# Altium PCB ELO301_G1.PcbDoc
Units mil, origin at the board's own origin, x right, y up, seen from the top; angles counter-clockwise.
Board outline 2755.91 x 1968.5 mil, 4 copper layers (Top Layer, GND, Senal-Potencia, Bottom Layer), stack 62.449 mil thick; 68 components, 51 nets, 254 pads, 188 vias.
Unrouted connection lines stored in the file: 32.
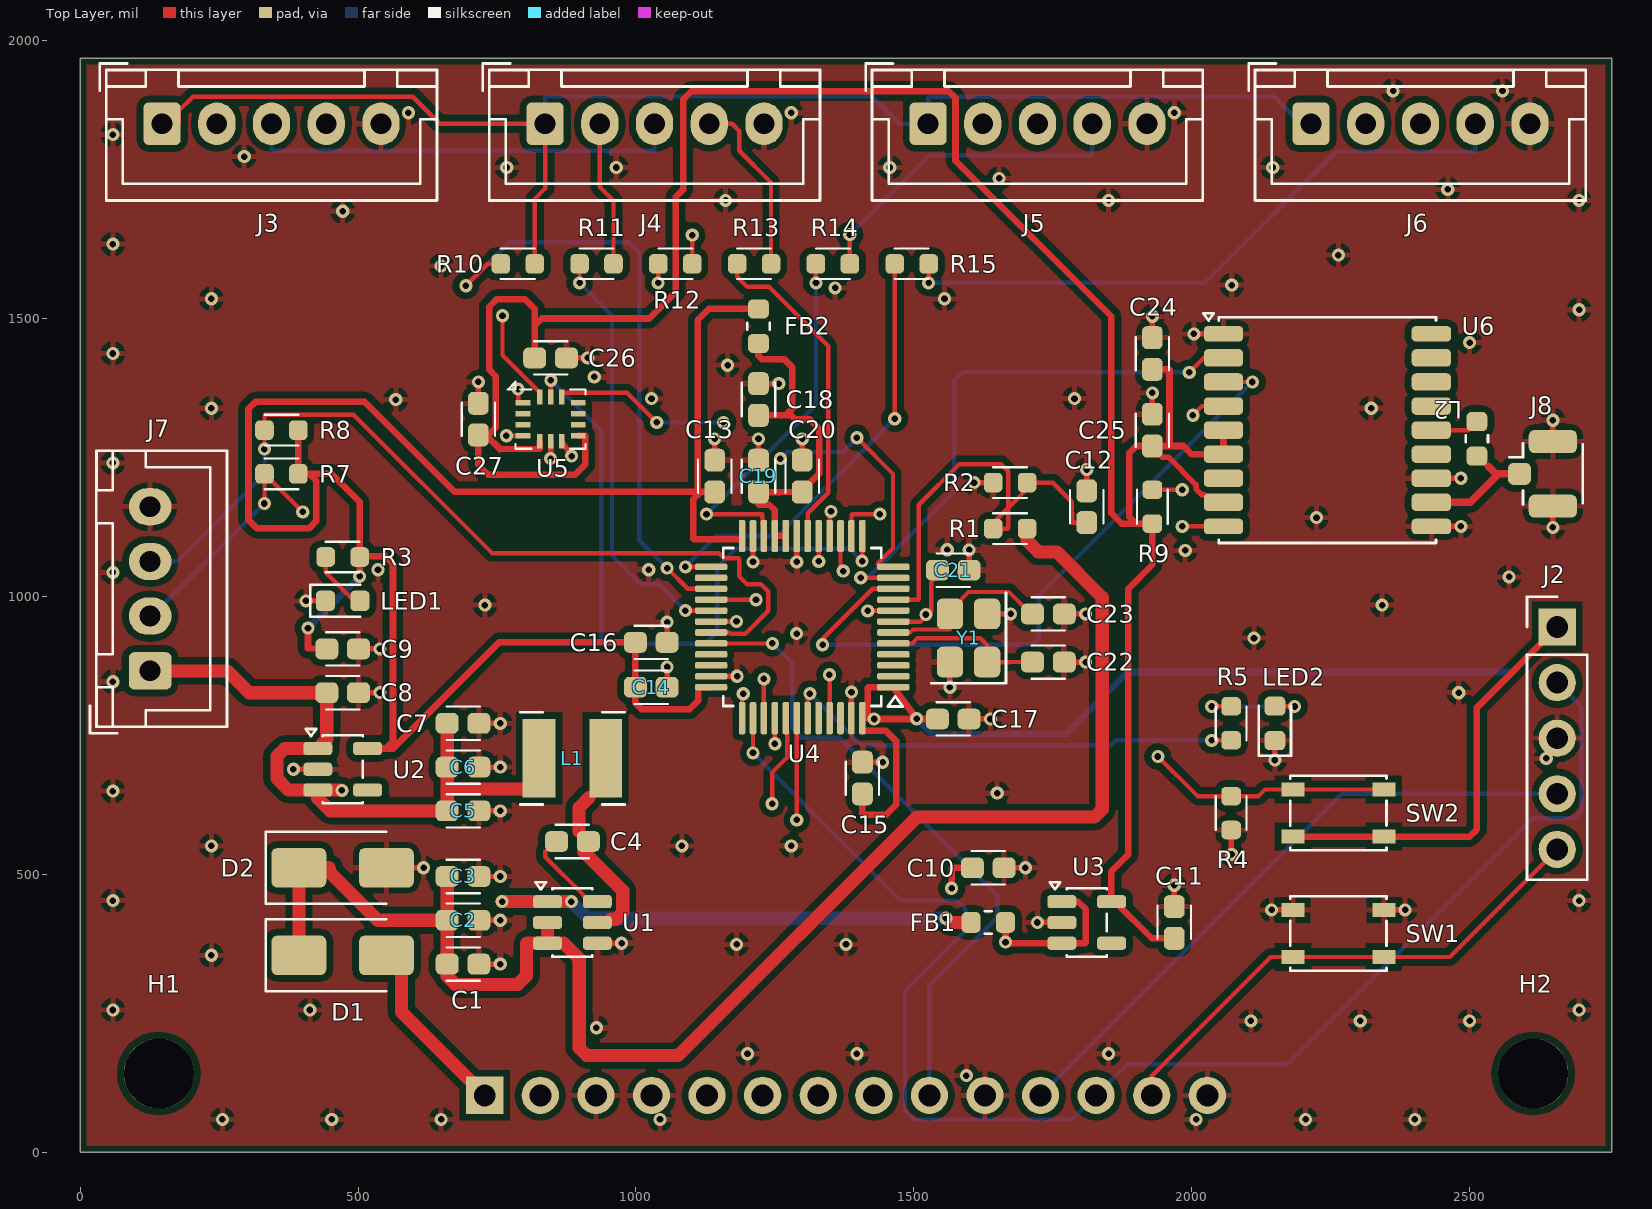
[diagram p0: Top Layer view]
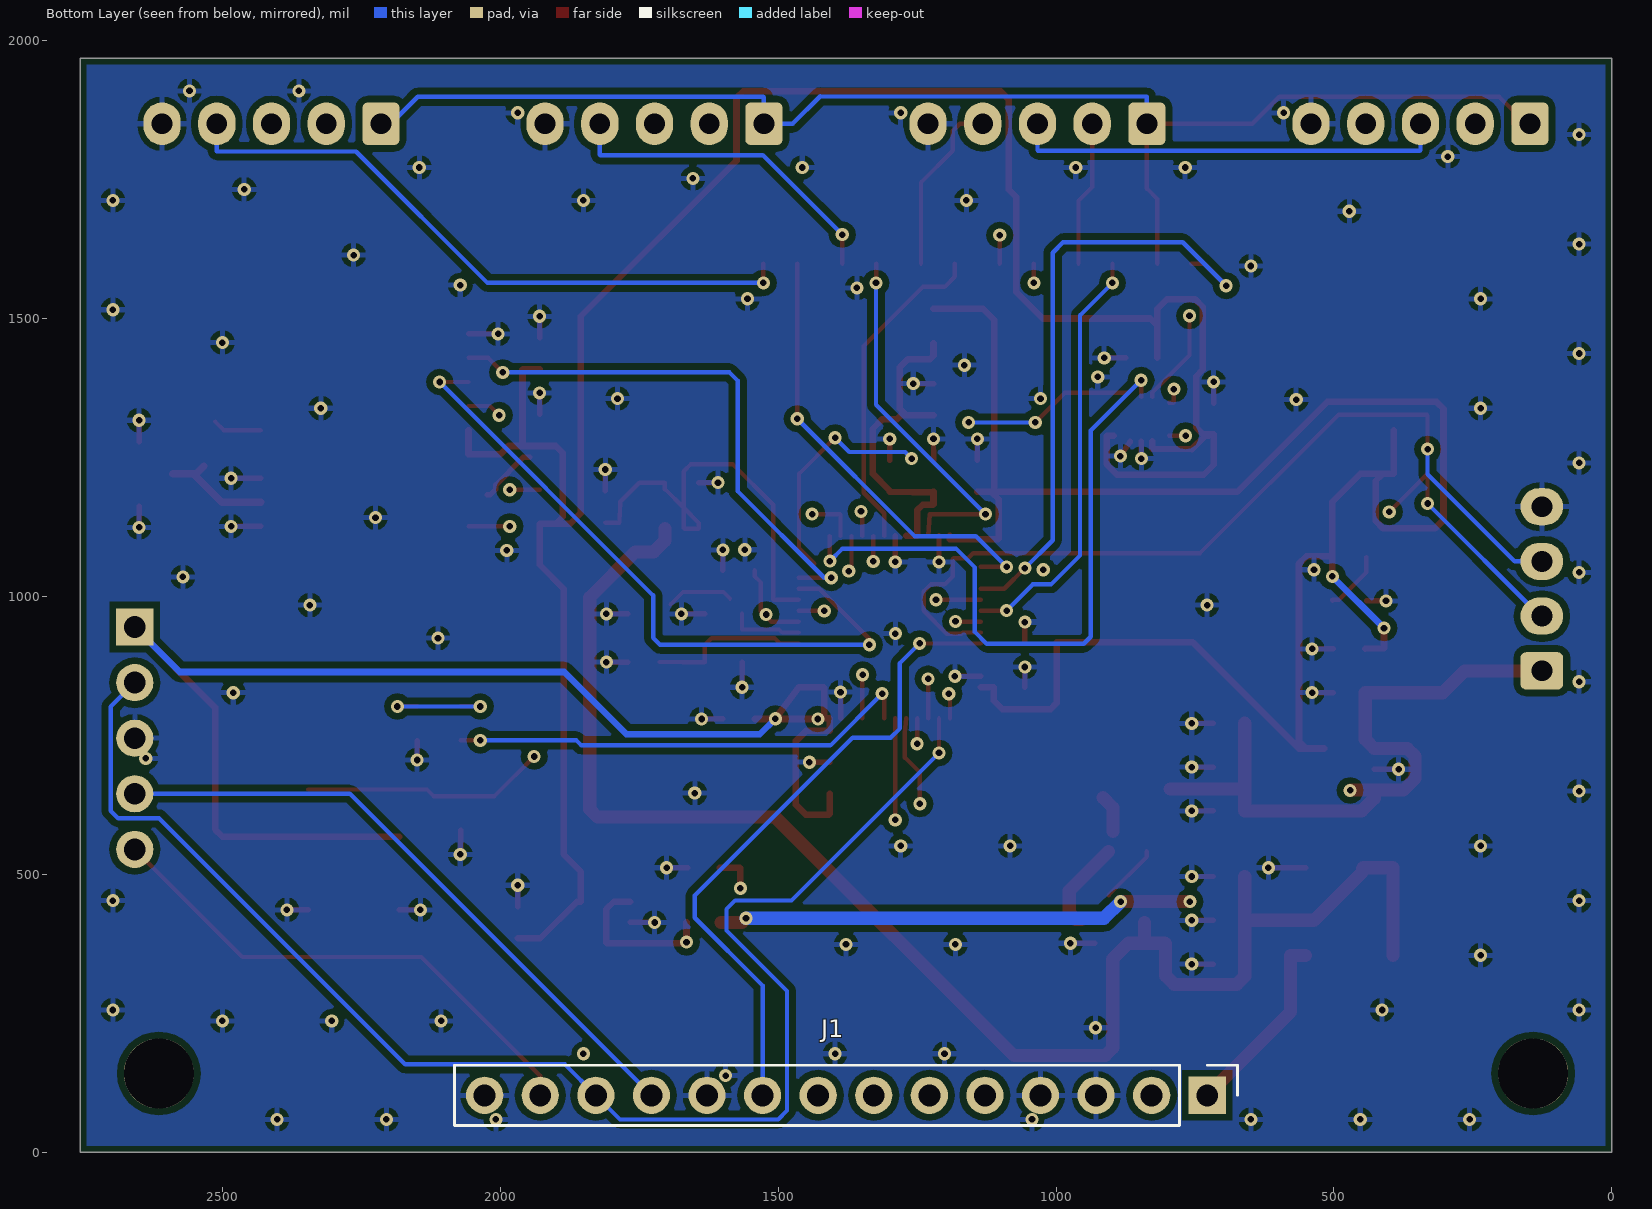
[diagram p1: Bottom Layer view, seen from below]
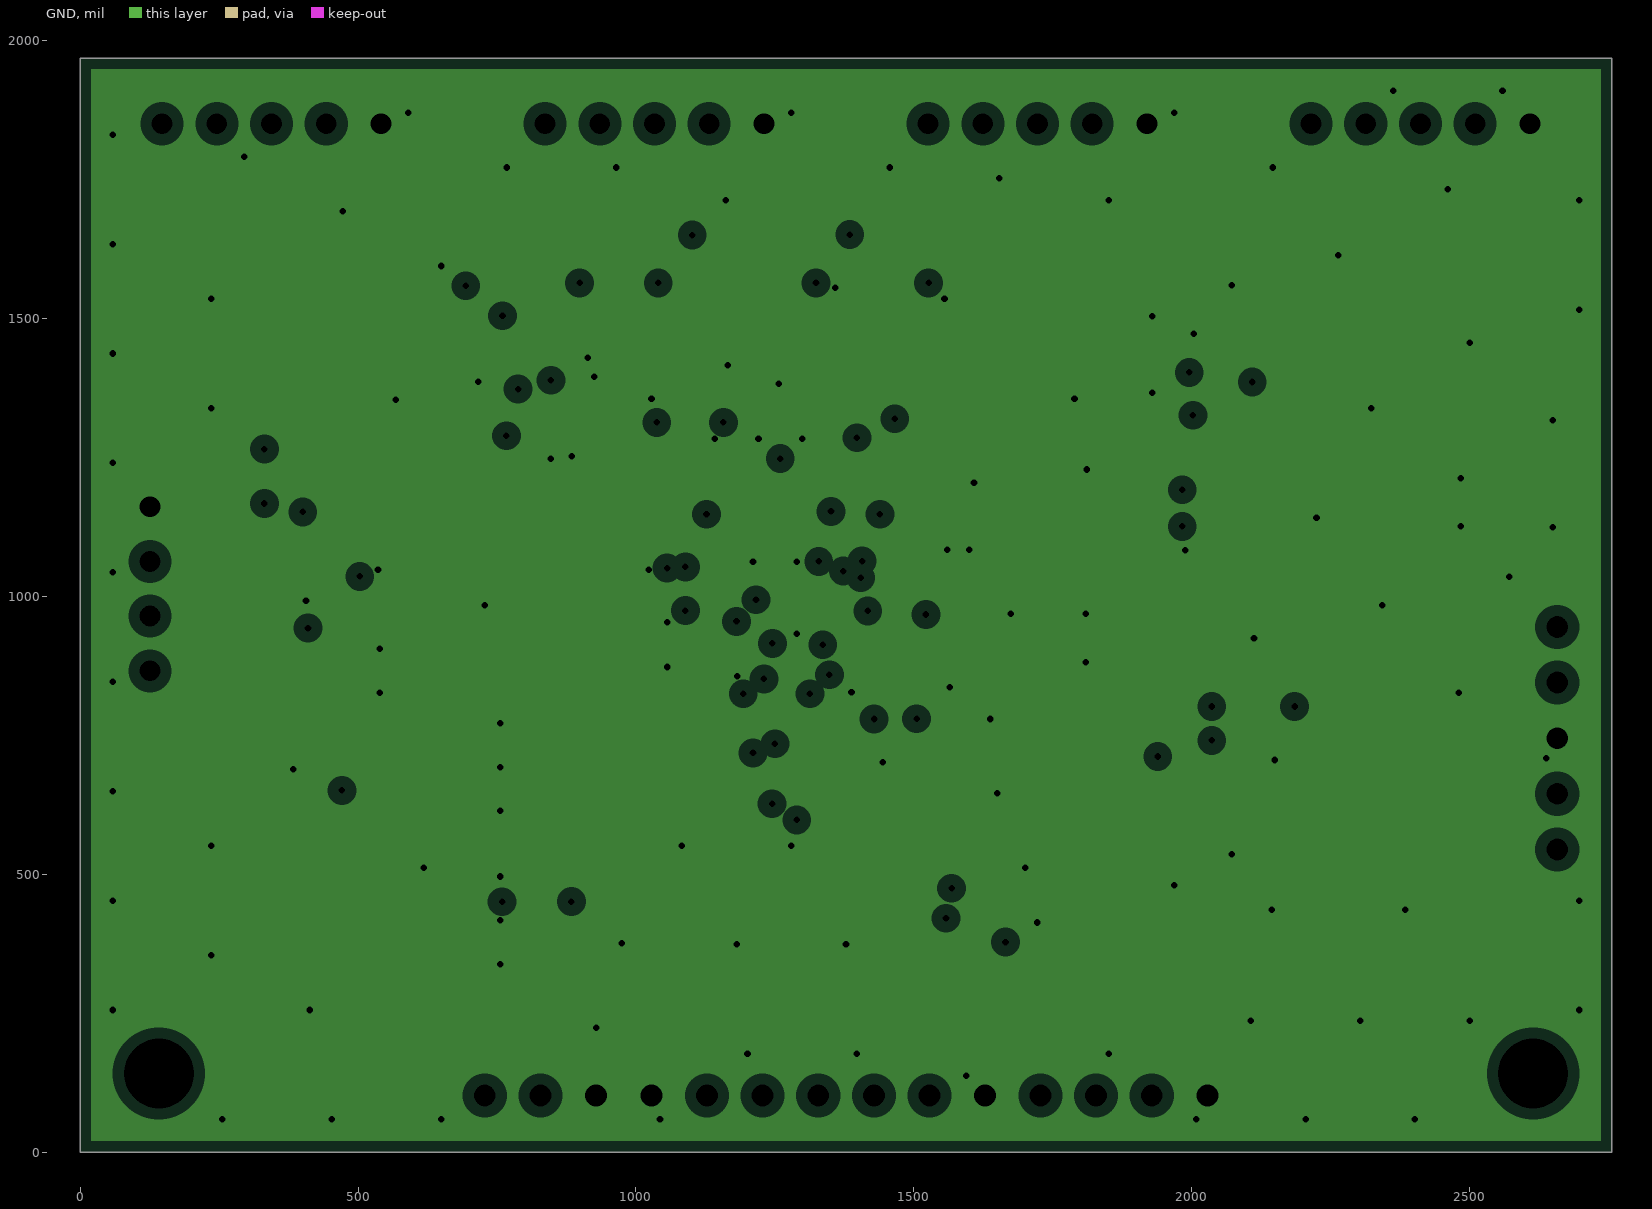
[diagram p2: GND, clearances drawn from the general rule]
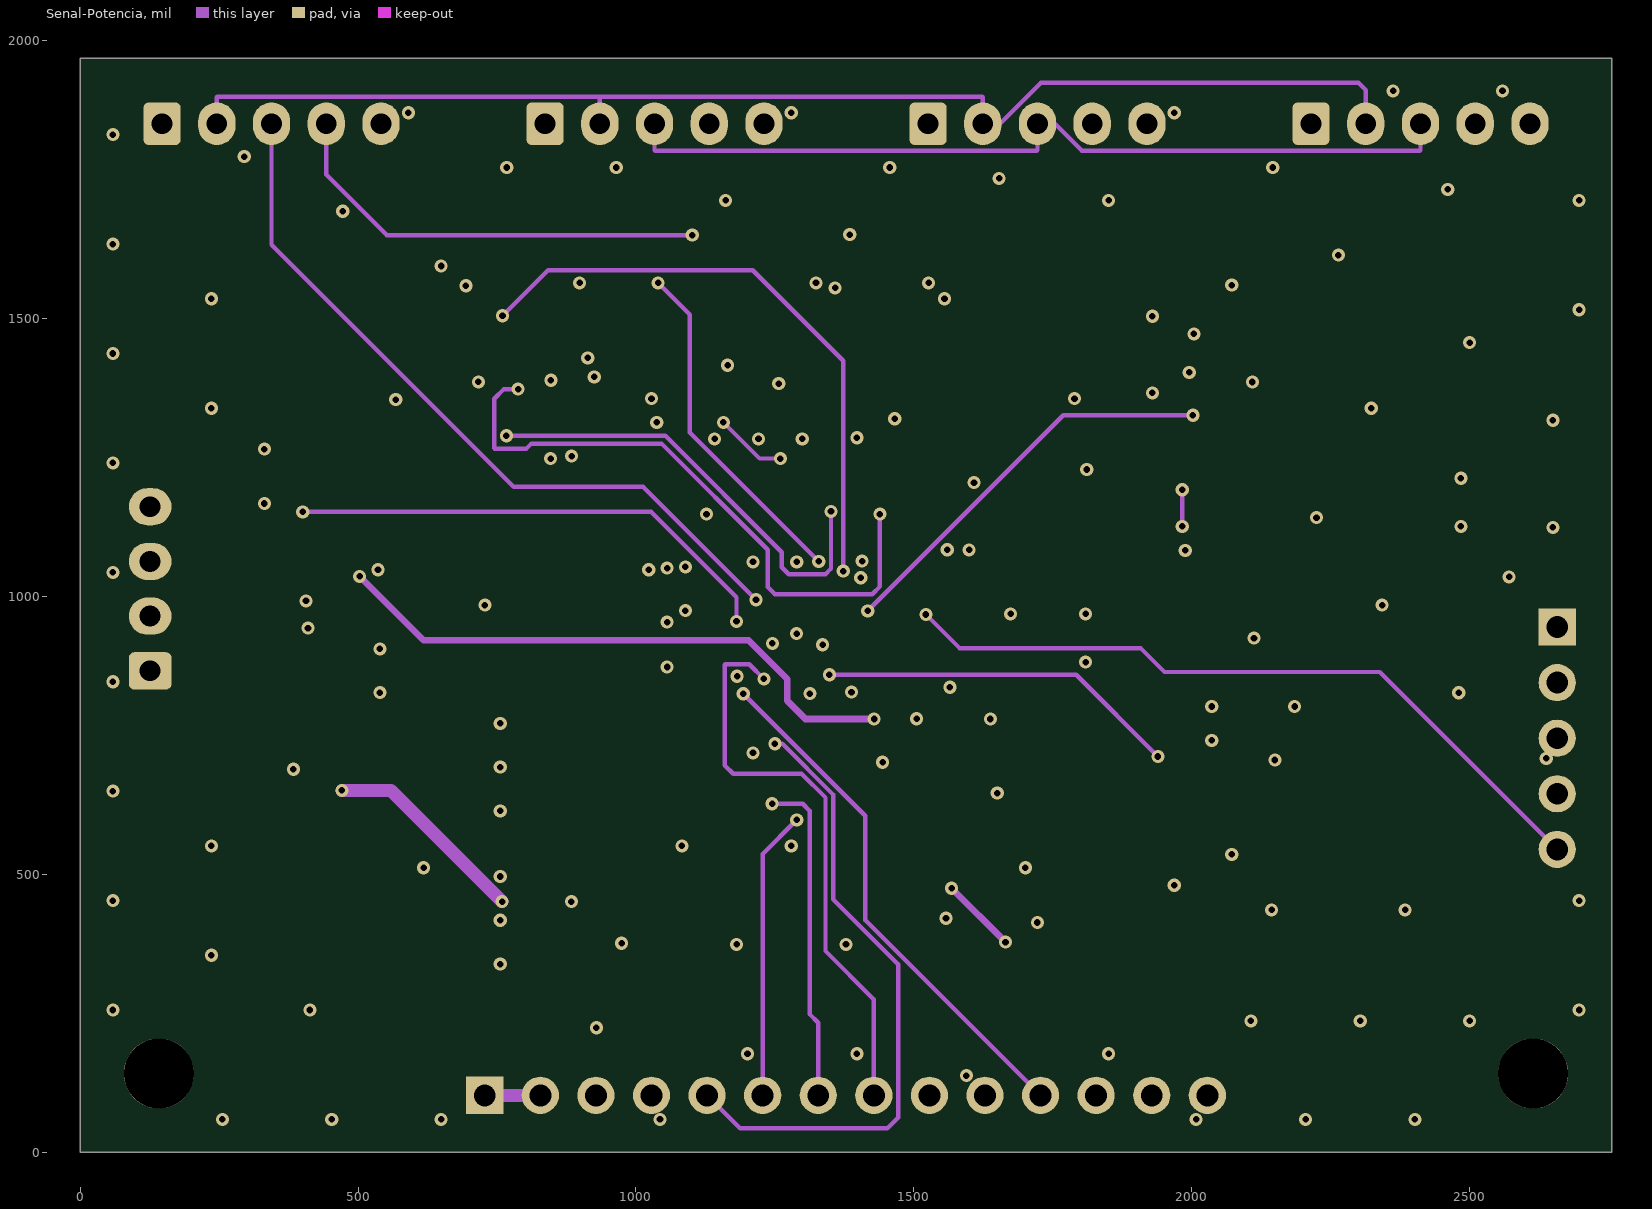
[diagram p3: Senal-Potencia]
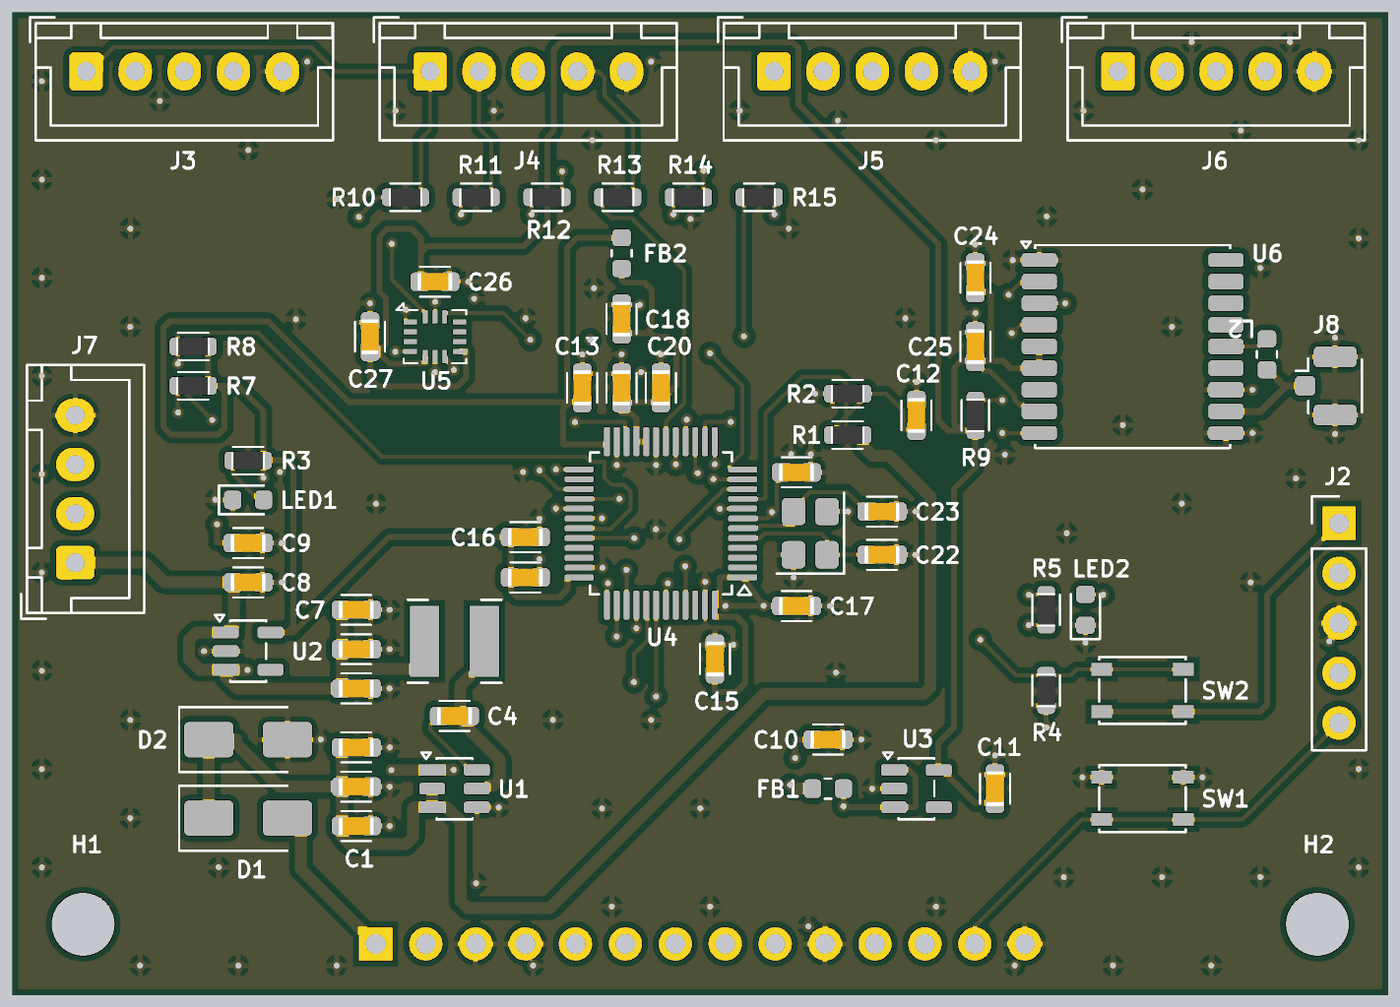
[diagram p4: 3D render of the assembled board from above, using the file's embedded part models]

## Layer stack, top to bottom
Top Solder: solder mask 0.4, Solder Resist, Dk 3.5
Top Layer: signal copper 1.378
Dielectric 1: prepreg 8.2835, PP 7628, Dk 4.4
GND: plane copper 0.5984, net GND
Dielectric2: core 41.9291, FR-4, Dk 4.6
Senal-Potencia: signal copper 0.5984
Dielectric3: prepreg 8.2835, PP 7628, Dk 4.4
Bottom Layer: signal copper 1.378
Bottom Solder: solder mask 0.4, Solder Resist, Dk 3.5

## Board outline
0,0 0,1968.5 2755.91,1968.5 2755.91,0

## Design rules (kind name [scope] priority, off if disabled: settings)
Clearance Clearance_Poligono [InPolygon] p1: gap=11.81 ignorepadtopadclearanceinfootprint=FALSE
Clearance [All] p2: gap=5.91 ignorepadtopadclearanceinfootprint=FALSE
HoleSize [All] p1: absolutevalues=TRUE maxlimit=137.8 minlimit=9.84 maxpercent=80.000 minpercent=20.000
MinimumSolderMaskSliver [All] p1: minsoldermaskwidth=2.76
PlaneClearance [All] p1: clearance=20
PlaneConnect [All] p1: planeconnectstyle=Relief reliefexpansion=20 reliefentries=4 reliefconductorwidth=10 reliefairgap=10
PolygonConnect [All] p1: connectstyle=Relief reliefconductorwidth=10 reliefentries=4 polygonreliefangle="90 Angle" airgapwidth=10
RoutingVias [All] p1: holewidth=11.81 width=23.62 viastyle="Through Hole" minholewidth=9.84 minwidth=19.68 maxholewidth=15.75 maxwidth=31.5
SilkToSolderMaskClearance [IsPad] p1: minsilkscreentomaskgap=3.94 clearancetoexposedcopper=TRUE
SolderMaskExpansion [All] p1: expansion=1.97 istentingtop=FALSE
SupplyNets "Schematic Supply Nets_3" [InNet('V_5V')] p1: voltage=0.000
SupplyNets "Schematic Supply Nets_2" [InNet('GND')] p2: voltage=0.000
SupplyNets "Schematic Supply Nets_1" [InNet('V3V3_MCU')] p3: voltage=0.000
SupplyNets "Schematic Supply Nets" [InNet('V3V3_SENS')] p4: voltage=0.000
Width Ancho_RF [InNet('RF_IN')] p1: maxlimit=13.78 minlimit=13.78 preferedwidth=13.78 minimp=50.000000 maximp=50.000000 favimp=50.000000
Width Ancho_Potencia [InNetClass('Potencia')] p2: maxlimit=78.74 minlimit=11.81 preferedwidth=23.62 minimp=50.000000 maximp=50.000000 favimp=50.000000
Width Ancho_Alimentacion [InNetClass('Alimentacion')] p3: maxlimit=78.74 minlimit=9.84 preferedwidth=11.81 minimp=50.000000 maximp=50.000000 favimp=50.000000
Width [All] p4: maxlimit=78.74 minlimit=5.91 preferedwidth=7.87 minimp=50.000000 maximp=50.000000 favimp=50.000000
25 further rules are at their usual default settings.

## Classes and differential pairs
net class Alimentacion: V3V3_MCU V3V3_SENS V5_SENS VDDA
net class Potencia: SW V_5V VIN_12V VIN_PROT
component class 04_Conectores: H1 H2 J1 J2 J3 J4 J5 J6 R10 R11 R12 R13 R14 R15
component class 03_Sensores: C24 C25 C26 C27 J7 J8 L2 R7 R8 R9 U5 U6
component class 02_MCU: C13 C14 C15 C16 C17 C18 C19 C20 C21 C22 C23 FB2 LED2 R4 R5 SW1 SW2 U4 Y1
component class 01_Alimentacion: C1 C2 C3 C4 C5 C6 C7 C8 C9 C10 C11 C12 D1 D2 FB1 L1 LED1 R1 R2 R3 U1 U2 U3

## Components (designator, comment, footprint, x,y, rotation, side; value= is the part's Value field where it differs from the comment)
C1 "10uF" "C0603 - MURATA" 689,338.6 r0 top
C2 "10uF" "C0603 - MURATA" 689,417.3 r0 top
C3 "10uF" "C0603 - MURATA" 689,496.1 r0 top
C4 "100nF" "C0603 - MURATA" 885.8,559.1 r0 top
C5 "22uF" "C0603 - MURATA" 689,614.2 r0 top
C6 "22uF" "C0603 - MURATA" 689,692.9 r0 top
C7 "22uF" "C0603 - MURATA" 689,771.7 r0 top
C8 "1uF" "C0603 - MURATA" 472.4,826.8 r0 top
C9 "1uF" "C0603 - MURATA" 472.4,905.5 r0 top
C10 "1uF" "C0603 - MURATA" 1633.9,511.8 r0 top
C11 "1uF" "C0603 - MURATA" 1968.5,413.4 r90 top
C12 "100nF" "C0603 - MURATA" 1811,1161.4 r90 top
C13 "100nF" "C0603 - MURATA" 1141.7,1216.5 r90 top
C14 "100nF" "C0603 - MURATA" 1027.6,836.6 r0 top
C15 "100nF" "C0603 - MURATA" 1407.5,673.2 r90 top
C16 "4.7uF" "C0603 - MURATA" 1027.6,917.3 r0 top
C17 "100nF" "C0603 - MURATA" 1570.9,779.5 r0 top
C18 "1uF" "C0603 - MURATA" 1220.5,1354.3 r90 top
C19 "100nF" "C0603 - MURATA" 1220.5,1216.5 r90 top
C20 "100nF" "C0603 - MURATA" 1299.2,1216.5 r90 top
C21 "100nF" "C0603 - MURATA" 1570.9,1047.2 r0 top
C22 "27pF C0G" "C0603 - MURATA" 1742.1,881.9 r0 top
C23 "27pF C0G" "C0603 - MURATA" 1742.1,968.5 r0 top
C24 "10uF" "C0603 - MURATA" 1929.1,1437 r90 top
C25 "100nF" "C0603 - MURATA" 1929.1,1299.2 r90 top
C26 "100nF" "C0603 - MURATA" 846.5,1429.1 r0 top
C27 "100nF" "C0603 - MURATA" 716.5,1318.9 r90 top
D1 "B240A" "SMA - DIODES" 472.4,354.3 r0 top
D2 "SMAJ15A" "SMA - DIODES" 472.4,511.8 r0 top
FB1 "220R@100MHz" "L0603 - GENERIC" 1633.9,413.4 r0 top
FB2 "220R@100MHz" "L0603 - GENERIC" 1220.5,1486.2 r90 top
H1 "M3" "M3 - HOLE" 141.7,141.7 r0 top
H2 "M3" "M3 - HOLE" 2614.2,141.7 r0 top
J1 "HDR 1x14" "HDR 1x14 2.54 - BOOMELE" 728,102.4 r270 bottom
J2 "HDR 1x05" "HDR 1x05 2.54 - BOOMELE" 2657.5,944.9 r0 top
J3 "FOC1" "B5B-XH-A - JST" 147.6,1850.4 r0 top
J4 "FOC2" "B5B-XH-A - JST" 836.6,1850.4 r0 top
J5 "FOC3" "B5B-XH-A - JST" 1525.6,1850.4 r0 top
J6 "FOC4" "B5B-XH-A - JST" 2214.6,1850.4 r0 top
J7 "B4B-XH-A" "B4B-XH-A - JST" 126,866.1 r90 top
J8 "U.FL" "U.FL - HIROSE" 2649.6,1220.5 r0 top
L1 "SRN4018-4R7M" "SRN4018 - BOURNS" 885.8,708.7 r180 top value=4.7uH
L2 "LQG18HN47NJ00D" "L0603 - GENERIC" 2513,1283.5 r270 top value=47nH
LED1 "Verde" "LED0603 - LITEON" 472.4,992.1 r0 top
LED2 "Rojo" "LED0603 - LITEON" 2149.6,771.7 r90 top
R1 "100k" "R0603 - YAGEO" 1673.2,1122 r0 top
R2 "12k" "R0603 - YAGEO" 1673.2,1204.7 r0 top
R3 "1k" "R0603 - YAGEO" 472.4,1070.9 r0 top
R4 "10k" "R0603 - YAGEO" 2070.9,610.2 r90 top
R5 "1k" "R0603 - YAGEO" 2070.9,771.7 r90 top
R7 "4.7k" "R0603 - YAGEO" 362.2,1220.5 r0 top
R8 "4.7k" "R0603 - YAGEO" 362.2,1299.2 r0 top
R9 "10k" "R0603 - YAGEO" 1929.1,1161.4 r90 top
R10 "33R" "R0603 - YAGEO" 787.4,1598.4 r0 top
R11 "33R" "R0603 - YAGEO" 929.1,1598.4 r0 top
R12 "33R" "R0603 - YAGEO" 1070.9,1598.4 r0 top
R13 "33R" "R0603 - YAGEO" 1212.6,1598.4 r0 top
R14 "33R" "R0603 - YAGEO" 1354.3,1598.4 r0 top
R15 "33R" "R0603 - YAGEO" 1496.1,1598.4 r0 top
SW1 "PTS810" "PTS810 - CK" 2263.8,393.7 r0 top
SW2 "PTS810" "PTS810 - CK" 2263.8,610.2 r0 top
U1 "AP63205" "TSOT-23-6 - DIODES" 885.8,413.4 r0 top
U2 "TLV75533" "SOT-23-5 - TI" 472.4,689 r0 top
U3 "TLV75533" "SOT-23-5 - TI" 1811,413.4 r0 top
U4 "STM32G431CBT6" "LQFP-48 - ST" 1299.2,944.9 r180 top
U5 "BMI270" "LGA-14 2.5x3.0 - BOSCH" 846.5,1318.9 r0 top
U6 "ATGM336H-5N31" "LCC-18 9.7x10.1 - ZKW" 2244.1,1299.2 r0 top
Y1 "25MHz" "ABM8 - ABRACON" 1598.4,925.2 r90 top

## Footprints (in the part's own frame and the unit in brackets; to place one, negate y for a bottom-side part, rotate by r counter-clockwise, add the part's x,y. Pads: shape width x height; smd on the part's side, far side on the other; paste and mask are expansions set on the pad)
"ABM8 - ABRACON" [mm] "Abracon ABM8G, Miniature Ceramic Crystal, 3.2x2.5mm package, SMD, http://www.abracon.com/Resonators/ABM8G.pdf"
  rrect42% 1.4x1.2 smd: 1(-1.1,-0.85) 2(1.1,-0.85) 3(1.1,0.85) 4(-1.1,0.85)
  silkscreen extent -2.06,-1.71 2.06,1.71
"B4B-XH-A - JST" [mm] "JST XH series connector, B4B-XH-A (http://www.jst-mfg.com/product/pdf/eng/eXH.pdf)"
  rrect29% 1.7x1.95 hole 0.95: 1(0,0)
  oval 1.7x1.95 hole 0.95: 2(2.5,0) 3(5,0) 4(7.5,0)
  silkscreen extent -2.85,-3.51 10.06,2.75
"B5B-XH-A - JST" [mm] "JST XH series connector, B5B-XH-A (http://www.jst-mfg.com/product/pdf/eng/eXH.pdf)"
  rrect29% 1.7x1.95 hole 0.95: 1(0,0)
  oval 1.7x1.95 hole 0.95: 2(2.5,0) 3(5,0) 4(7.5,0) 5(10,0)
  silkscreen extent -2.85,-3.51 12.56,2.75
"C0603 - MURATA" [mm]
  rrect50% 1.05x0.95 smd: 1(-0.725,0) 2(0.725,0)
  silkscreen extent -0.76,-0.76 0.76,0.76, body extent -0.9,-0.45 0.9,0.45, height 0.9
"HDR 1x05 2.54 - BOOMELE" [mm] "Through hole straight pin header, 1x05, 2.54mm pitch, single row"
  rect 1.7x1.7 hole 1: 1(0,0)
  round 1.7 hole 1: 2(0,-2.54) 3(0,-5.08) 4(0,-7.62) 5(0,-10.16)
  silkscreen extent -1.38,-11.54 1.38,1.38
"HDR 1x14 2.54 - BOOMELE" [mm] "Through hole straight pin header, 1x14, 2.54mm pitch, single row"
  rect 1.7x1.7 hole 1: 1(0,0)
  round 1.7 hole 1: 2(0,-2.54) 3(0,-5.08) 4(0,-7.62) 5(0,-10.16) 6(0,-12.7) 7(0,-15.24) 8(0,-17.78) 9(0,-20.32) 10(0,-22.86) 11(0,-25.4) 12(0,-27.94) 13(0,-30.48) 14(0,-33.02)
  silkscreen extent -1.38,-34.4 1.38,1.38
"L0603 - GENERIC" [mm] "Inductor SMD 0603 (1608 Metric), square (rectangular) end terminal, IPC-7351 nominal, (Body size source: http://www.tortai-tech.com/upload/download/2011102023233369053.pdf)"
  rrect50% 0.875x0.95 smd: 1(-0.788,0) 2(0.788,0)
  silkscreen extent -0.16,-0.51 0.16,0.51
"LCC-18 9.7x10.1 - ZKW" [mm] "ublox MAX 6/7/8, (https://www.u-blox.com/sites/default/files/MAX-8-M8-FW3_HardwareIntegrationManual_%28UBX-15030059%29.pdf)"
  rrect50% 1.8x0.7 smd: 1(-4.75,4.4) 9(-4.75,-4.4) 10(4.75,-4.4) 18(4.75,4.4)
  rrect50% 1.8x0.8 smd: 2(-4.75,3.3) 3(-4.75,2.2) 4(-4.75,1.1) 5(-4.75,0) 6(-4.75,-1.1) 7(-4.75,-2.2) 8(-4.75,-3.3) 11(4.75,-3.3) 12(4.75,-2.2) 13(4.75,-1.1) 14(4.75,0) 15(4.75,1.1) 16(4.75,2.2) 17(4.75,3.3)
  silkscreen extent -5.67,-5.16 4.96,5.34
"LED0603 - LITEON" [mm] "LED SMD 0603 (1608 Metric), square (rectangular) end terminal, IPC-7351 nominal, (Body size source: http://www.tortai-tech.com/upload/download/2011102023233369053.pdf)"
  rrect50% 0.875x0.95 smd: 1(-0.788,0) 2(0.788,0)
  silkscreen extent -1.48,-0.73 0.8,0.74
"LGA-14 2.5x3.0 - BOSCH" [mm] "LGA-14 Bosch https://ae-bst.resource.bosch.com/media/_tech/media/datasheets/BST-BMI160-DS000-07.pdf"
  rect 0.675x0.25 smd: 1(-1.262,0.75) 2(-1.262,0.25) 3(-1.262,-0.25) 4(-1.262,-0.75) 8(1.263,-0.75) 9(1.263,-0.25) 10(1.263,0.25) 11(1.263,0.75)
  rect 0.25x0.675 smd: 5(-0.5,-1.012) 6(0,-1.012) 7(0.5,-1.012) 12(0.5,1.012) 13(0,1.012) 14(-0.5,1.012)
  silkscreen extent -1.96,-1.35 1.6,1.71
"LQFP-48 - ST" [mm] "LQFP, 48 Pin (JEDEC MS-026 variation BBC, 1.40mm body thickness, https://www.jedec.org/document_search?search_api_views_fulltext=MS-026, https://www.analog.com/media/en/package-pcb-resources/package/pkg_pdf/ltc-legacy-lqfp/05081760_a_lx48.pdf)"
  rrect50% 1.475x0.3 smd: 1(-4.163,2.75) 2(-4.163,2.25) 3(-4.163,1.75) 4(-4.163,1.25) 5(-4.163,0.75) 6(-4.163,0.25) 7(-4.163,-0.25) 8(-4.163,-0.75) 9(-4.163,-1.25) 10(-4.163,-1.75) 11(-4.163,-2.25) 12(-4.163,-2.75) 25(4.163,-2.75) 26(4.163,-2.25) 27(4.163,-1.75) 28(4.163,-1.25) 29(4.163,-0.75) 30(4.163,-0.25) 31(4.163,0.25) 32(4.163,0.75) 33(4.163,1.25) 34(4.163,1.75) 35(4.163,2.25) 36(4.163,2.75)
  rrect50% 0.3x1.475 smd: 13(-2.75,-4.163) 14(-2.25,-4.163) 15(-1.75,-4.163) 16(-1.25,-4.163) 17(-0.75,-4.163) 18(-0.25,-4.163) 19(0.25,-4.163) 20(0.75,-4.163) 21(1.25,-4.163) 22(1.75,-4.163) 23(2.25,-4.163) 24(2.75,-4.163) 37(2.75,4.163) 38(2.25,4.163) 39(1.75,4.163) 40(1.25,4.163) 41(0.75,4.163) 42(0.25,4.163) 43(-0.25,4.163) 44(-0.75,4.163) 45(-1.25,4.163) 46(-1.75,4.163) 47(-2.25,4.163) 48(-2.75,4.163)
  silkscreen extent -4.59,-3.61 3.61,3.63
"M3 - HOLE" [mm] "Mounting Hole 3.2mm, M3, no annular, generated by kicad-footprint-generator mountinghole.py"
  round 3.2 hole 3.2 unplated: ""(0,0)
"PTS810 - CK" [mm] "C&K Components, PTS 810 Series, Microminiature SMT Top Actuated, http://www.ckswitches.com/media/1476/pts810.pdf"
  rect 1.05x0.65 smd: 1(-2.075,1.075) 1(2.075,1.075) 2(-2.075,-1.075) 2(2.075,-1.075)
  silkscreen extent -2.2,-1.7 2.2,1.7
"R0603 - YAGEO" [mm]
  rrect50% 0.85x0.9 smd: 1(-0.775,0) 2(0.775,0)
  silkscreen extent -0.78,-0.7 0.78,0.7, body extent -0.85,-0.45 0.85,0.45, height 0.55
"SMA - DIODES" [mm] "Diode SMA (DO-214AC)"
  rrect28% 2.5x1.8 smd: 1(-2,0) 2(2,0)
  silkscreen extent -3.51,-1.65 2,1.65
"SOT-23-5 - TI" [mm] "SOT, 5 Pin (JEDEC MO-178 Var AA https://www.jedec.org/document_search?search_api_views_fulltext=MO-178)"
  rrect50% 1.325x0.6 smd: 1(-1.137,0.95) 2(-1.137,0) 3(-1.137,-0.95) 4(1.138,-0.95) 5(1.138,0.95)
  silkscreen extent -1.69,-1.56 0.91,1.84
"SRN4018 - BOURNS" [mm] "Bourns SRN4018 series SMD inductor, https://www.bourns.com/docs/Product-Datasheets/SRN4018.pdf"
  rect 1.5x3.6 smd: 1(-1.525,0) 2(1.525,0)
  silkscreen extent -2.39,-2.11 2.39,2.11
"TSOT-23-6 - DIODES" [mm] "TSOT, 6 Pin (https://www.jedec.org/sites/default/files/docs/MO-193D.pdf variant AA)"
  rrect50% 1.325x0.6 smd: 1(-1.137,0.95) 2(-1.137,0) 3(-1.137,-0.95) 4(1.138,-0.95) 5(1.138,0) 6(1.138,0.95)
  silkscreen extent -1.69,-1.56 0.91,1.84
"U.FL - HIROSE" [mm] "Hirose U.FL Coaxial (https://www.hirose.com/en/product/document?clcode=CL0331-0472-2-01&productname=U.FL-R-SMT-1(01)&series=U.FL&documenttype=2DDrawing&lang=en&documentid=0000940668)"
  rrect50% 1.05x1 smd: 1(-1.525,0)
  rrect48% 2.2x1.05 smd: 2(0,-1.475) 2(0,1.475)
  silkscreen extent -1.99,-1.4 1.36,1.4

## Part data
C1 C2 C3 C24: library part "CAP - GENERIC", .Case/Package=0603, .Voltage Rating (DC)=25V, Manufacturer=Murata, Manufacturer Part Number=GRM188R61E106MA73D
C4 C12 C13 C14 C15 C17 C19 C20 C21 C25 C26 C27: library part "CAP - GENERIC", .Case/Package=0603, .Voltage Rating (DC)=50V, Manufacturer=Murata, Manufacturer Part Number=GRM188R71H104KA93D
C5 C6 C7: library part "CAP - GENERIC", .Case/Package=0603, .Voltage Rating (DC)=10V, Manufacturer=Murata, Manufacturer Part Number=GRM188R61A226ME15D
C8 C9 C10 C11 C18: library part "CAP - GENERIC", .Case/Package=0603, .Voltage Rating (DC)=25V, Manufacturer=Murata, Manufacturer Part Number=GRM188R61E105KA12D
C16: library part "CAP - GENERIC", .Case/Package=0603, .Voltage Rating (DC)=10V, Manufacturer=Murata, Manufacturer Part Number=GRM188R61A475KE15D
C22 C23: library part "CAP - GENERIC", .Case/Package=0603, .Voltage Rating (DC)=50V, Manufacturer=Murata, Manufacturer Part Number=GRM1885C1H270JA01D
D1: library part B240A-13-F, "Schottky diode", Manufacturer="Diodes Inc."
D2: library part SMAJ15A-13-F, "Diodes SMAJ15A TVS unidireccional 400 W, 15 V de trabajo, SMA", Manufacturer="Diodes Inc."
FB1 FB2: library part "FERRITE - GENERIC", "Ferrite bead, small symbol", Manufacturer=Murata, Manufacturer Part Number=BLM18PG221SN1D
H1 H2: library part "MOUNTING HOLE - M3", "Mounting Hole without connection", Manufacturer=-
J1: library part "CONN - 1x14", "Generic connector, single row, 01x14, script generated (kicad-library-utils/schlib/autogen/connector/)", Manufacturer=BOOMELE, Manufacturer Part Number="2.54-1*40P (1x14)"
J2: library part "CONN - 1x05", "Generic connector, single row, 01x05, script generated (kicad-library-utils/schlib/autogen/connector/)", Manufacturer=BOOMELE, Manufacturer Part Number="2.54-1*40P (1x5)"
J3 J4 J5 J6: library part "CONN - 1x05", "Generic connector, single row, 01x05, script generated (kicad-library-utils/schlib/autogen/connector/)", Manufacturer=JST, Manufacturer Part Number=B5B-XH-A(LF)(SN)
J7: library part "CONN - 1x04", "Generic connector, single row, 01x04, script generated (kicad-library-utils/schlib/autogen/connector/)", Manufacturer=JST, Manufacturer Part Number=B4B-XH-A(LF)(SN)
J8: library part U.FL-R-SMT-1(10), "coaxial connector (BNC, SMA, SMB, SMC, Cinch/RCA, LEMO, ...)", Manufacturer=Hirose
L1: library part "INDUCTOR - GENERIC", .Max DC Current=2.0A, .RMS Current (Irms)=1.9A, .Value=4.7uH, Manufacturer=Bourns
L2: library part "INDUCTOR - GENERIC", .Max DC Current=400mA, .Value=47nH, Manufacturer=Murata
LED1: library part "LED - GENERIC", "Light emitting diode", Manufacturer=Lite-On, Manufacturer Part Number=LTST-C191KGKT
LED2: library part "LED - GENERIC", "Light emitting diode", Manufacturer=Lite-On, Manufacturer Part Number=LTST-C191KRKT
R1: library part "RESISTOR - GENERIC", .Case/Package=0603, .Tolerance=1%, Manufacturer=Yageo, Manufacturer Part Number=RC0603FR-07100KL
R2: library part "RESISTOR - GENERIC", .Case/Package=0603, .Tolerance=1%, Manufacturer=Yageo, Manufacturer Part Number=RC0603FR-0712KL
R3 R5: library part "RESISTOR - GENERIC", .Case/Package=0603, .Tolerance=1%, Manufacturer=Yageo, Manufacturer Part Number=RC0603FR-071KL
R4 R9: library part "RESISTOR - GENERIC", .Case/Package=0603, .Tolerance=1%, Manufacturer=Yageo, Manufacturer Part Number=RC0603FR-0710KL
R7 R8: library part "RESISTOR - GENERIC", .Case/Package=0603, .Tolerance=1%, Manufacturer=Yageo, Manufacturer Part Number=RC0603FR-074K7L
R10 R11 R12 R13 R14 R15: library part "RESISTOR - GENERIC", .Case/Package=0603, .Tolerance=1%, Manufacturer=Yageo, Manufacturer Part Number=RC0603FR-0733RL
SW1 SW2: library part "PTS810 SJM 250 SMTR LFS", "Push button switch, generic, two pins", Manufacturer=C&K
U1: library part AP63205WU-7, "2A, 1.1MHz Buck DC/DC Converter, fixed 5.0V output voltage, TSOT-23-6", Manufacturer="Diodes Inc."
U2 U3: library part TLV75533PDBVR, "TI TLV75533 LDO 500 mA, salida fija 3,3 V, SOT-23-5", Manufacturer="Texas Instruments"
U4: "STMicroelectronics Arm Cortex-M4 MCU, 128KB flash, 32KB RAM, 170 MHz, 1.71-3.6V, 38 GPIO, LQFP48", Manufacturer=STMicroelectronics
U5: "Bosch BMI270 IMU 6 ejes (acelerometro + giroscopio), SPI/I2C, LGA-14 2.5x3.0mm", Manufacturer="Bosch Sensortec"
U6: "ZKW ATGM336H-5N31 modulo GNSS GPS+BDS, UART + 1PPS, LCC-18 9.7x10.1mm (huella compatible u-blox MAX)", Manufacturer="ZKW (Hangzhou ZhongKe)"
Y1: library part ABM8-25.000MHZ-B2-T, "Four pin crystal, GND on pins 2 and 4", Manufacturer=Abracon

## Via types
v1: diameter 23.62, hole 11.81, Top Layer to Bottom Layer, tented both sides, 188 vias

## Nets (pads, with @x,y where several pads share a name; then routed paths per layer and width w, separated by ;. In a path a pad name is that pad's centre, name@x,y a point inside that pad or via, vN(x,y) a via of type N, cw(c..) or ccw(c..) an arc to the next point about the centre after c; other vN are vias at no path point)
BOOT0: R4.2 SW2.1 U4.45 | length 1171
  Top Layer w7.87: v1(1348,859) 1348.41,858.59 U4.45 ; v1(1939,712) 2010.29,640.71 R4.2 2120,640.71 2131.81,652.52 2182.11,652.52 SW2.1@2345.49,652.52
  Senal-Potencia w7.87: v1(1348,859) 1792,859 v1(1939,712)
BST: C4.1 U1.6 | length 107.3
  Top Layer w7.87: 836.61,541.34 836.61,531.5 905.51,462.6
FOC1_CS: J3.4 R12.2 | length 846.7
  Top Layer w7.87: R12.2 v1(1101.41,1650)
  Senal-Potencia w7.87: J3.4 442.88,1759 551.88,1650 v1(1101.41,1650)
FOC2_CS: J4.4 R13.2 | length 322.2
  Top Layer w7.87: J4.4 1173.1,1850.4 1186,1837.5 1186,1802 1243.11,1744.89 R13.2
FOC3_CS: J5.4 R14.2 | length 603.7
  Top Layer w7.87: R14.2 v1(1384.81,1651)
  Bottom Layer w7.87: v1(1384.81,1651) 1527.81,1794 1819.88,1794 1820.88,1795 J5.4
FOC4_CS: J6.4 R15.2 | length 1164.8
  Top Layer w7.87: v1(1526.61,1564) R15.2
  Bottom Layer w7.87: v1(1526.61,1564) 2023,1564 2259,1800 2509.88,1801 J6.4
FOC_BUS_MOSI: J3.2 J4.2 J5.2 J6.2 R11.2 | length 2570.1
  Top Layer w7.87: J4.2 935.03,1736.59 959.61,1712 R11.2
  Senal-Potencia w7.87: J3.2 246.03,1898 247.03,1899 934.03,1899 935.03,1898 ; J4.2 935.03,1898 ; J6.2 2313.03,1910.97 2300,1924 1728.6,1924 1655,1850.4 J5.2 1624.03,1898 1623.03,1899 936.03,1899 935.03,1898
FOC_BUS_SCK: J3.1 J4.1 J5.1 J6.1 R10.2 | length 2518.9
  Top Layer w7.87: J3.1 147.6,1850 178,1850 178,1874 203,1899 598.4,1899 647,1850.4 J4.1 836.6,1733.69 817.91,1715 R10.2
  Bottom Layer w7.87: J4.1 836.6,1899 1424.4,1900 1474,1850.4 J5.1 1525.6,1898 1526.6,1899 2148.4,1899 2197,1850.4 J6.1
FOC_CS1: R12.1 U4.17 | length 701.2
  Top Layer w7.87: v1(1040,1564) 1040.39,1564.39 R12.1 ; U4.17 1328.73,1063.27 v1(1329,1063)
  Senal-Potencia w7.87: v1(1040,1564) 1097,1507 1097,1295 v1(1329,1063)
FOC_CS2: R13.1 U4.18 | length 596
  Top Layer w7.87: R13.1 1182.09,1574.91 1200,1557 1239.5,1557 1346,1450.5 1346,1186.5 1309.04,1149.54 U4.18
FOC_CS3: R14.1 U4.22 | length 671.4
  Top Layer w7.87: v1(1127,1148) 1227,1148 U4.22 ; R14.1 1323.79,1564.21 v1(1324,1564)
  Bottom Layer w7.87: v1(1127,1148) 1324,1345 v1(1324,1564)
FOC_CS4: R15.1 U4.25 | length 812.1
  Top Layer w7.87: v1(1089,1053.17) U4.25 ; v1(1465.59,1319.59) R15.1
  Bottom Layer w7.87: v1(1089,1053.17) 1144.33,1108.5 1254.5,1108.5 v1(1465.59,1319.59)
GND: C1.2 C2.2 C3.2 C5.2 C6.2 C7.2 C8.2 C9.2 C10.2 C11.2 C12.2 C13.2 C14.2 C15.2 C16.2 C17.2 C18.2 C19.2 C20.2 C21.2 C22.2 C23.2 C24.2 C25.2 C26.2 C27.2 D2.2 J1.3 J1.4 J1.10 J1.14 J2.3 J3.5 J4.5 J5.5 J6.5 J7.4 J8.2 LED1.1 LED2.1 R2.1 R4.1 SW1.1 U1.4 U2.2 U3.2 U4.19 U4.23 U4.35 U4.47 U5.6 U5.7 U6.1 U6.10 U6.12 Y1.2 Y1.4 | length 1976
  Top Layer w9.84: v1(383.82,689.02) U2.2 ; v1(406.46,992.09) LED1.1 ; C8.2 v1(539.33,826.81) ; C9.2 v1(539.33,905.51) ; D2.2 v1(618.07,511.81) ; C27.2 v1(716.5,1385.83) ; C1.2 v1(755.94,338.58) ; C2.2 v1(755.94,417.28) ; C3.2 v1(755.94,496.1) ; C5.2 v1(755.94,614.21) ; C6.2 v1(755.94,692.91) ; C7.2 v1(755.94,771.69) ; v1(846.5,1248.03) U5.6 ; U5.7 v1(884.41,1252.48) ; C26.2 v1(913.43,1429.09) ; U1.4 v1(974.37,375.98) ; C14.2 v1(1056.14,873.03) ; C16.2 v1(1056.14,953.7) ; U4.35 v1(1182.09,856.3) ; C13.2 v1(1141.69,1283.43) ; U4.23 v1(1210.63,1062.01) ; C19.2 v1(1220.51,1283.43) ; C18.2 v1(1256.93,1382.83) ; v1(1289.37,1062.01) U4.19 ; C20.2 v1(1299.21,1283.43) ; U4.47 v1(1387.8,827.76) ; C15.2 v1(1443.9,701.73) ; v1(1564.92,836.61) Y1.4 ; C17.2 v1(1637.83,779.49) ; C21.2 v1(1599.45,1083.62) ; v1(1608.23,1204.69) R2.1 ; Y1.2 v1(1674.02,968.5) ; C10.2 v1(1700.83,511.81) ; v1(1722.4,413.39) U3.2 ; C22.2 v1(1809.02,881.89) ; C23.2 v1(1809.02,968.5) ; C12.2 v1(1810.98,1228.35) ; C25.2 v1(1929.09,1366.14) ; C24.2 v1(1929.09,1503.94) ; C11.2 v1(1968.5,480.32) ; v1(2003.94,1472.44) U6.1 ; v1@2070.91,545.24 R4.1 ; v1(2143.74,436.02) SW1.1@2182.11,436.02 ; v1(2149.61,705.75) LED2.1 ; SW1.1@2345.49,436.02 v1(2383.9,436.02) ; U6.10 v1(2484.25,1125.98) ; U6.12 v1(2484.25,1212.6) ; v1(2649.61,1124.06) J8.2@2649.6,1162.43 ; J8.2@2649.6,1278.57 v1(2649.61,1316.97)
  other v1: 255.91,59.06 452.76,59.06 649.61,59.06 1043.31,59.06 2007.87,59.06 2204.72,59.06 2401.57,59.06 1594.49,137.8 1200.79,177.17 1397.64,177.17 1850.39,177.17 929,224 2106.3,236.22 2303.15,236.22 2500,236.22 59.06,255.91 413.39,255.91 2696.85,255.91 236.22,354.33 1181.1,374.02 1377.95,374.02 59.06,452.76 2696.85,452.76 2072,536 236.22,551.18 1082.68,551.18 1279.53,551.18 1650,646 59.06,649.61 2637.8,708.66 2480.32,826.77 59.06,846.46 2112,925 1289,933 728.35,984.25 2342.52,984.25 2571,1035 59.06,1043.31 536,1048 1023,1048 1988.19,1082.68 1560,1084 2224.41,1141.73 59.06,1240.16 236.22,1338.58 2322.83,1338.58 568,1354 1028,1356 1789,1356 925,1395 1165,1416 59.06,1437.01 2500,1456.69 2696.85,1515.75 236.22,1535.43 1555.12,1535.43 1358.27,1555.12 2072,1560 649.61,1594.49 2263.78,1614.17 59.06,1633.86 472.44,1692.91 1161.42,1712.6 1850.39,1712.6 2696.85,1712.6 2460.63,1732.28 1653.54,1751.97 767.72,1771.65 964.57,1771.65 1456.69,1771.65 2145.67,1771.65 295.28,1791.34 59.06,1830.71 590.55,1870.08 1279.53,1870.08 1968.5,1870.08 2362.2,1909.45 2559.06,1909.45
GNSS_PPS: U4.8 U6.4 | length 839
  Top Layer w7.87: v1(1417,974) 1417.43,974.43 U4.8 ; v1(2001.98,1326) 2018.49,1342.51 U6.4
  Senal-Potencia w7.87: v1(1417,974) 1769,1326 v1(2001.98,1326)
I2C_TOF_SCL: J7.3 R8.1 U4.31 | length 1589.1
  Top Layer w7.87: v1(331.69,1265) R8.1 331.69,1326 332.69,1327 492,1327 741,1078 1149,1078 1158,1069 1184,1069 1186,1067 1186,1036 1200,1022 1225,1022 1238,1009 1238,974 1197,933 1170,933 1167.94,935.06 U4.31
  Bottom Layer w7.87: J7.3 175,1062.95 331.69,1219.64 v1(331.69,1265)
I2C_TOF_SDA: J7.2 R7.1 U4.30 | length 1373.5
  Top Layer w7.87: v1(331.69,1167.21) R7.1 332,1220.5 v1(400.5,1152) ; U4.30 1180.74,954.74 v1(1181,955)
  Senal-Potencia w7.87: v1(400.5,1152) 1027.6,1152 1181,998.6 v1(1181,955)
  Bottom Layer w7.87: J7.2 129,964.53 v1(331.69,1167.21)
IMU_INT1: U4.16 U5.4 | length 885.3
  Top Layer w7.87: v1(767,1289) 767.37,1289.37 U5.4 ; U4.16 1348.41,1150.41 v1(1351,1153)
  Senal-Potencia w7.87: v1(767,1289) 1053,1289 1262.5,1079.5 1262.5,1052.5 1275,1040 1341,1040 1351,1050 v1(1351,1153)
LED_HB: R5.1 U4.43 | length 845.9
  Top Layer w7.87: U4.43 1309.04,821.13 v1(1312.96,825.04) ; v1(2036,741) 2036.19,741.19 R5.1
  Bottom Layer w7.87: v1(1312.96,825.04) 1406,732 1854,732 1863,741 v1(2036,741)
NetL2_1: L2.1 U6.14 | length 88.2
  Top Layer w7.87: U6.14 2497.64,1299.21 L2.1@2512.99,1314.57
NetLED1_2: LED1.2 R3.1 | length 111.5
  Top Layer w7.87: R3.1 441.89,1043.11 491,994 503.4,994 LED1.2
NetLED2_2: LED2.2 R5.2 | length 219.7
  Top Layer w7.87: v1(2036,802) 2036.21,802.21 R5.2 ; LED2.2 2184.3,802.7 v1(2185,802)
  Bottom Layer w7.87: v1(2036,802) v1(2185,802)
NetR9_2: R9.2 U6.9 | length 193.9
  Top Layer w7.87: R9.2 v1(1983,1191.91) ; v1(1983,1125.97) U6.9
  Senal-Potencia w7.87: v1(1983,1125.97) v1(1983,1191.91)
NRST: C21.1 J1.13 J2.5 SW1.2 U4.7 | length 2400.8
  Top Layer w7.87: U4.7 1512.5,954.74 v1@1523.51,965.75 ; v1(1521.76,967.5) v1@1523.51,965.75 ; C21.1 1542.36,1036.27 1531,1024.92 1531,973.24 v1@1523.51,965.75 ; J1.13 1928,137.38 2142,351.38 2182.11,351.38 2345.49,351.38 2463.98,351.38 J2.5
  Senal-Potencia w7.87: v1(1521.76,967.5) 1582.26,907 1908,907 1951,864 2338.4,864 J2.5
OSC_IN: C22.1 U4.5 Y1.1 | length 290.3
  Top Layer w7.87: U4.5 1497,915.37 1506.63,925 1619.37,925 1631.87,912.5 Y1.1 1672,881.89 C22.1
OSC_OUT: C23.1 U4.6 Y1.3 | length 252.4
  Top Layer w7.87: U4.6@1462.99,935.04 1492.91,935.04 1498.43,940.55 1564.96,940.55 Y1.3@1564.96,968.5 ; 1586.61,996.06 1598.43,1007.87 1671.26,1007.87 1692.91,986.22
RF_IN: J8.1 L2.2 U6.11 | length 196.2
  Top Layer w13.78: U6.11 2501.18,1169.29 2552.36,1220.47 J8.1@2589.37,1220.47 ; 2533.46,1234.25 2545.28,1222.44
SPI_FOC_MISO: J3.3 J4.3 J5.3 J6.3 U4.28 | length 3760.6
  Top Layer w7.87: U4.28 v1(1216,994.11)
  Senal-Potencia w7.87: J3.3 344.45,1632.55 780,1197 1013.11,1197 v1(1216,994.11) ; J4.3 1033.45,1803 1034.45,1802 1721.45,1802 1722.45,1803 J5.3 1754,1850.4 1802.4,1802 2410.45,1802 2411.45,1803 J6.3
  Bottom Layer w7.87: J3.3 344.45,1803 345.45,1802 1032.45,1802 1033.45,1803 J4.3
SPI_FOC_MOSI: R11.1 U4.29 | length 768.3
  Top Layer w7.87: v1(898.59,1564) R11.1 ; v1(1089,974.43) U4.29
  Bottom Layer w7.87: v1(898.59,1564) 957,1505.59 957,1073.72 1009.11,1021.61 1041.82,1021.61 v1(1089,974.43)
SPI_FOC_SCK: R10.1 U4.27 | length 1114.1
  Top Layer w7.87: v1(694,1559) 733.4,1598.4 R10.1 ; v1(1056,1051) 1093.2,1013.8 U4.27
  Bottom Layer w7.87: v1(694,1559) 772,1637 987.5,1637 1006,1618.5 1006,1101 v1(1056,1051)
SPI_IMU_CS: U4.12 U5.12 | length 856.7
  Top Layer w7.87: U5.12@870.08,1366.14 984.25,1366.14 v1(1037.4,1312.99) ; v1(1397.64,1285.43) 1462.6,1220.47 1462.6,1086.61 1435.04,1059.06
  Senal-Potencia w7.87: v1(1157.48,1312.99) 1222.44,1248.03 v1(1259.84,1248.03)
  Bottom Layer w7.87: v1(1037.4,1312.99) v1(1157.48,1312.99) ; v1(1259.84,1248.03) 1271.65,1259.84 1372.05,1259.84 v1(1397.64,1285.43)
SPI_IMU_MISO: U4.14 U5.1 | length 1247.4
  Top Layer w7.87: v1(788,1373) 788,1348.43 U5.1 ; U4.14 1387.78,1147 1388.78,1148 v1(1439,1148)
  Senal-Potencia w7.87: v1(788,1373) 762.5,1373 745,1355.5 745,1267 746,1266 803,1266 812,1275 1046,1275 1237,1084 1237,1017 1250,1004 1425,1004 1439,1018 v1(1439,1148)
SPI_IMU_MOSI: U4.15 U5.14 | length 1332.2
  Top Layer w7.87: v1(760,1505) 760,1433.82 826.82,1367 U5.14 ; U4.15 1368.1,1050.4 v1(1373,1045.5)
  Senal-Potencia w7.87: v1(760,1505) 842,1587 1210,1587 1373,1424 v1(1373,1045.5)
SPI_IMU_SCK: U4.13 U5.13 | length 1197.7
  Top Layer w7.87: U5.13 846.5,1388.5 v1(847,1389) ; v1(1407,1063.47) 1407.47,1063.94 U4.13
  Bottom Layer w7.87: v1(847,1389) 937.5,1298.5 937.5,927.5 950,915 1125,915 1146,936 1146,1052 1180,1086 1384.47,1086 v1(1407,1063.47)
SPI_SUP_MISO: J1.7 U4.41 | length 756.5
  Top Layer w7.87: v1(1245,626.99) 1245,683 1272,710 1272,753.67 U4.41
  Senal-Potencia w7.87: v1(1245,626.99) 1300,626.99 1312.51,614.48 1312.51,248.49 1328,233 J1.7
SPI_SUP_MOSI: J1.6 U4.42 | length 704
  Top Layer w7.87: v1(1289.36,598) U4.42
  Senal-Potencia w7.87: J1.6 1228,536.64 v1(1289.36,598)
SPI_SUP_NSS: J1.8 U4.39 | length 1109.9
  Top Layer w7.87: U4.39 v1(1230.3,851.65)
  Senal-Potencia w7.87: v1(1230.3,851.65) 1204,877.95 1161,877.95 1160,876.95 1160,696 1175,681 1298,681 1341,638 1341,362 1428,275 J1.8
SPI_SUP_SCK: J1.5 U4.40 | length 1195.1
  Top Layer w7.87: v1(1250,735) U4.40
  Senal-Potencia w7.87: J1.5 1187.4,43 1452.5,43 1472,62.5 1472,338 1354.78,455.22 1354.78,643.71 1263.49,735 v1(1250,735)
SUP_IRQ: J1.9 U4.32 | length 1181.4
  Top Layer w7.87: U4.32 v1(1245.63,915.37)
  Bottom Layer w7.87: v1(1245.63,915.37) 1281,880 1281,762.5 1297.5,746 1366,746 1650,462 1650,422 1528,300 J1.9
SW: C4.2 L1.1 U1.5 | length 234.5
  Top Layer w23.62: 897.64,576.77 897.64,620.08 915.35,637.8 ; C4.2@905.51,541.34 976.38,470.47 976.38,431.1 964.57,419.29 U1.5@954.72,419.29
SWCLK: J1.12 J2.2 U4.38 | length 2671.2
  Top Layer w7.87: v1(1210.62,718.38) U4.38
  Bottom Layer w7.87: v1(1210.62,718.38) 1476,453 1577.5,453 1593,437.5 1593,399 1484,290 1484,75 1500,59 1784.6,59 J1.12 1883.6,158 2171,158 2614,601 2687.5,601 2701,614.5 2701,801.4 J2.2
SWDIO: J1.11 J2.4 U4.37 | length 2143
  Top Layer w7.87: U4.37 1190.93,822.72 v1(1193.11,824.89)
  Senal-Potencia w7.87: v1(1193.11,824.89) 1412.75,605.25 1412.75,417.65 J1.11
  Bottom Layer w7.87: J1.11 2270.5,644.9 J2.4
UART_GNSS_RX: U4.11 U6.2 | length 991.6
  Top Layer w7.87: v1(1404.5,1033.48) U4.11 ; v1(1995.5,1403) 2021.62,1429.12 U6.2
  Bottom Layer w7.87: v1(1404.5,1033.48) 1417,1033.48 1573.02,1189.5 1573.02,1388.52 1587.5,1403 v1(1995.5,1403)
UART_GNSS_TX: U4.10 U6.3 | length 1240.6
  Top Layer w7.87: v1(1336,913) 1336,923.8 1426,1013.8 U4.10 ; U6.3 v1(2109,1385.81)
  Bottom Layer w7.87: v1(1336,913) 1712.5,913 1725,925.5 1725,1001.81 v1(2109,1385.81)
V3V3_MCU: C9.1 C13.1 C14.1 C15.1 C16.1 C17.1 FB2.2 J2.1 R3.2 R7.2 R8.2 SW2.2 U2.5 U4.1 U4.24 U4.36 U4.48 | length 7437.9
  Top Layer w11.81: R8.2 R7.2 412.5,1220.5 ; v1(410,943) 410,906.5 C9.1 ; v1(503,1036) 502.91,1036.09 R3.2 R3.2@502.91,1072 ; U2.5 550,726.4 ; U4.36 1112,836.63 1112,812.5 1096.5,797 1010.06,797 999.06,808 C14.1 C16.1 753.9,917.3 563,726.4 550,726.4 ; C13.1 1115.96,1187.96 ; U4.24 1190.93,1103 1104,1103 1103,1104 1103,1175 1115.96,1187.96 ; FB2.2 1131.2,1517.2 1111,1497 1111,1188.96 1112,1187.96 ; C15.1 1407.5,608.67 1409,607.17 1450.17,607.17 1468,625 1468,740 1450,758 1407.47,758 U4.48 1416,781 1417,782 1417,835.63 1418,836.63 U4.1 v1(1505,780) ; v1(1428.5,779.5) v1@1505.5,779.5 ; SW2.2@2182.11,567.88 2345.49,567.88 2500,567.88 2513,580.88 2513,800.4 J2.1 ; 412.5,1220.5 452.77,1220.5 502.91,1170.36 R3.2@502.91,1072 ; 412.5,1220.5 425,1208 425,1135.5 412.5,1123 317.5,1123 303,1137.5 303,1337.5 315.5,1350 512,1350 674.04,1187.96 1112,1187.96 ; R3.2@502.91,1072 550,1072 563,1059 563,739.4 550,726.4 ; 1112,1187.96 1115.96,1187.96 ; v1(1505,780) C17.1 v1@1505.5,779.5 ; v1(1505,780) v1@1505.5,779.5
  Senal-Potencia w11.81: v1(503,1036) 618,921 1202.5,921 1272.5,851 1272.5,812 1305,779.5 v1(1428.5,779.5)
  Bottom Layer w11.81: v1(410,943) v1(503,1036) ; v1(1505,780) 1533,752 1773,752 1885,864 2576.6,864 J2.1
V3V3_SENS: C11.1 C24.1 C25.1 C26.1 C27.1 R9.1 U3.5 U5.5 U5.8 U6.5 U6.6 U6.8 | length 4464.7
  Top Layer w9.84: 1946.85,1250 1958.66,1250 2007.87,1200.79 2007.87,1192.91 2017.72,1183.07 2023.62,1183.07
  Top Layer w11.81: C26.1 817.96,1487.5 ; U5.5 826.82,1265.5 755.36,1265 732.18,1288.18 C27.1 ; U5.8 909,1289.37 909,1237.5 890.5,1219 734.5,1219 716.5,1237 C27.1 ; C24.1 1959,1408.46 1960,1407.46 1960,1271.66 1959,1270.66 ; C11.1 1928,384.86 1862.05,450.8 U3.5 1855,450.8 1855,505 1886,536 1886,1013.9 1929.1,1057 R9.1 1900,1130.89 ; U6.5 U6.6 1999.76,1255.89 1985,1270.66 1959,1270.66 ; C27.1 716.5,1292 736,1292 748,1304 748,1396 736,1408 736,1521 750,1535 800,1535 817.96,1517.04 817.96,1487.5 ; 817.96,1487.5 830.46,1500 1024,1500 1072,1548 1072,1719 1085,1732 1085,1894 1100,1909 1562.5,1909 1575,1896.5 1575,1784 1855,1504 1855,1150 1874.11,1130.89 1900,1130.89 ; 1900,1130.89 1887.5,1143.39 1887.5,1258.16 1900,1270.66 C25.1 1959,1270.66
V5_SENS: C10.1 FB1.2 U3.1 U3.3 | length 500.5
  Top Layer w11.81: v1(1568,474.9) 1568,510.8 1569,511.8 C10.1 ; v1(1664.9,378) v1@1664.9,378.1 ; FB1.2 v1@1664.9,378.1 ; U3.1 1795.81,450.8 1809.11,437.5 1809.11,377 1808.11,376 U3.3 1667,376 v1@1664.9,378.1
  Senal-Potencia w11.81: v1(1568,474.9) v1(1664.9,378)
V_5V: C5.1 C6.1 C7.1 C8.1 FB1.1 J7.1 L1.2 U1.1 U2.1 U2.3 | length 2455.6
  Top Layer w23.62: J7.1 265,866.1 304.3,826.8 C8.1 443.86,742.64 U2.1 367.9,726.4 354,712.5 354,672.6 375,651.6 U2.3 ; v1(471,651) 470.4,651.6 U2.3 ; C7.1 C6.1 C5.1 450,614.2 427.62,636.58 U2.3 ; 671.26,653.54 795.28,653.54 ; v1(759.2,450.8) U1.1 883.8,450.8 v1(884,451) ; v1(1557.9,421) 1565.5,413.4 FB1.1
  Senal-Potencia w23.62: v1(471,651) 559,651 v1(759.2,450.8)
  Bottom Layer w23.62: v1(884,451) 914,421 v1(1557.9,421)
VDDA: C18.1 C19.1 C20.1 FB2.1 U4.20 U4.21 | length 629.3
  Top Layer w11.81: C19.1 C19.1@1220.5,1187 ; C18.1 1269.26,1325.76 ; FB2.1 1220.5,1433 1226.5,1427 1266.5,1427 1281,1412.5 1281,1337.5 1269.26,1325.76 ; U4.20 U4.21 1249.99,1155 1239.99,1165 1221.5,1165 1220.5,1166 C19.1@1220.5,1187 ; C19.1@1220.51,1187 C20.1 1299.2,1190.2 1330,1221 1330,1301.5 1312.5,1319 1285.76,1319 1279,1325.76 1269.26,1325.76
VIN_12V: D1.2 J1.1 J1.2 | length 440.9
  Top Layer w23.62: D1.2 578,354.3 578,252.4 J1.1
  Senal-Potencia w23.62: J1.1 J1.2
VIN_PROT: C1.1 C2.1 C3.1 D1.1 D2.1 R1.2 U1.2 U1.3 | length 2875
  Top Layer w23.62: D1.1 D2.1 448,511.8 449,510.8 449,504 535.7,417.3 C2.1 ; C3.1 C2.1 ; U1.2 U1.3 ; R1.2 1703.71,1100 1723.71,1080 1757,1080 1839,998 1839,617 1825,603 1505,603 1076,174 911.5,174 898,187.5 898,348 870,376 U1.3 ; C2.1 C1.1 660.46,316.54 675,302 787.5,302 803,317.5 803,375 804,376 U1.3
VIN_SENSE: C12.1 R1.1 R2.2 U4.9 | length 808.5
  Top Layer w7.87: U4.9 1508,994.11 1509,995.11 1509,1165 1582,1238 1657,1238 1670,1225 1670,1159.31 ; C12.1 1785.43,1132.86 1784.29,1170.41 1750,1204.7 R2.2 1703.71,1193.02 1670,1159.31 ; 1670,1159.31 1670,1123 1669,1122 R1.1 1642.69,1132 1670,1159.31
pads on no net: H1. H2. U2.4 U3.4 U4.2 U4.3 U4.4 U4.26 U4.33 U4.34 U4.44 U4.46 U5.2 U5.3 U5.9 U5.10 U5.11 U6.7 U6.13 U6.15 U6.16 U6.17 U6.18

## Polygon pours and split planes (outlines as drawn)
GND on Bottom Layer "GND_Bottom" (solid, remove dead copper, pour order 1): 11.81,11.81 2744.09,11.81 2744.09,1956.69 11.81,1956.69
GND on Top Layer "GND_Top" (solid, remove dead copper, pour order 0): 11.81,11.81 2744.09,11.81 2744.09,1956.69 11.81,1956.69
GND on GND (split plane): 2735.81,20.1 20.1,20.1 20.1,1948.41 2735.81,1948.41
